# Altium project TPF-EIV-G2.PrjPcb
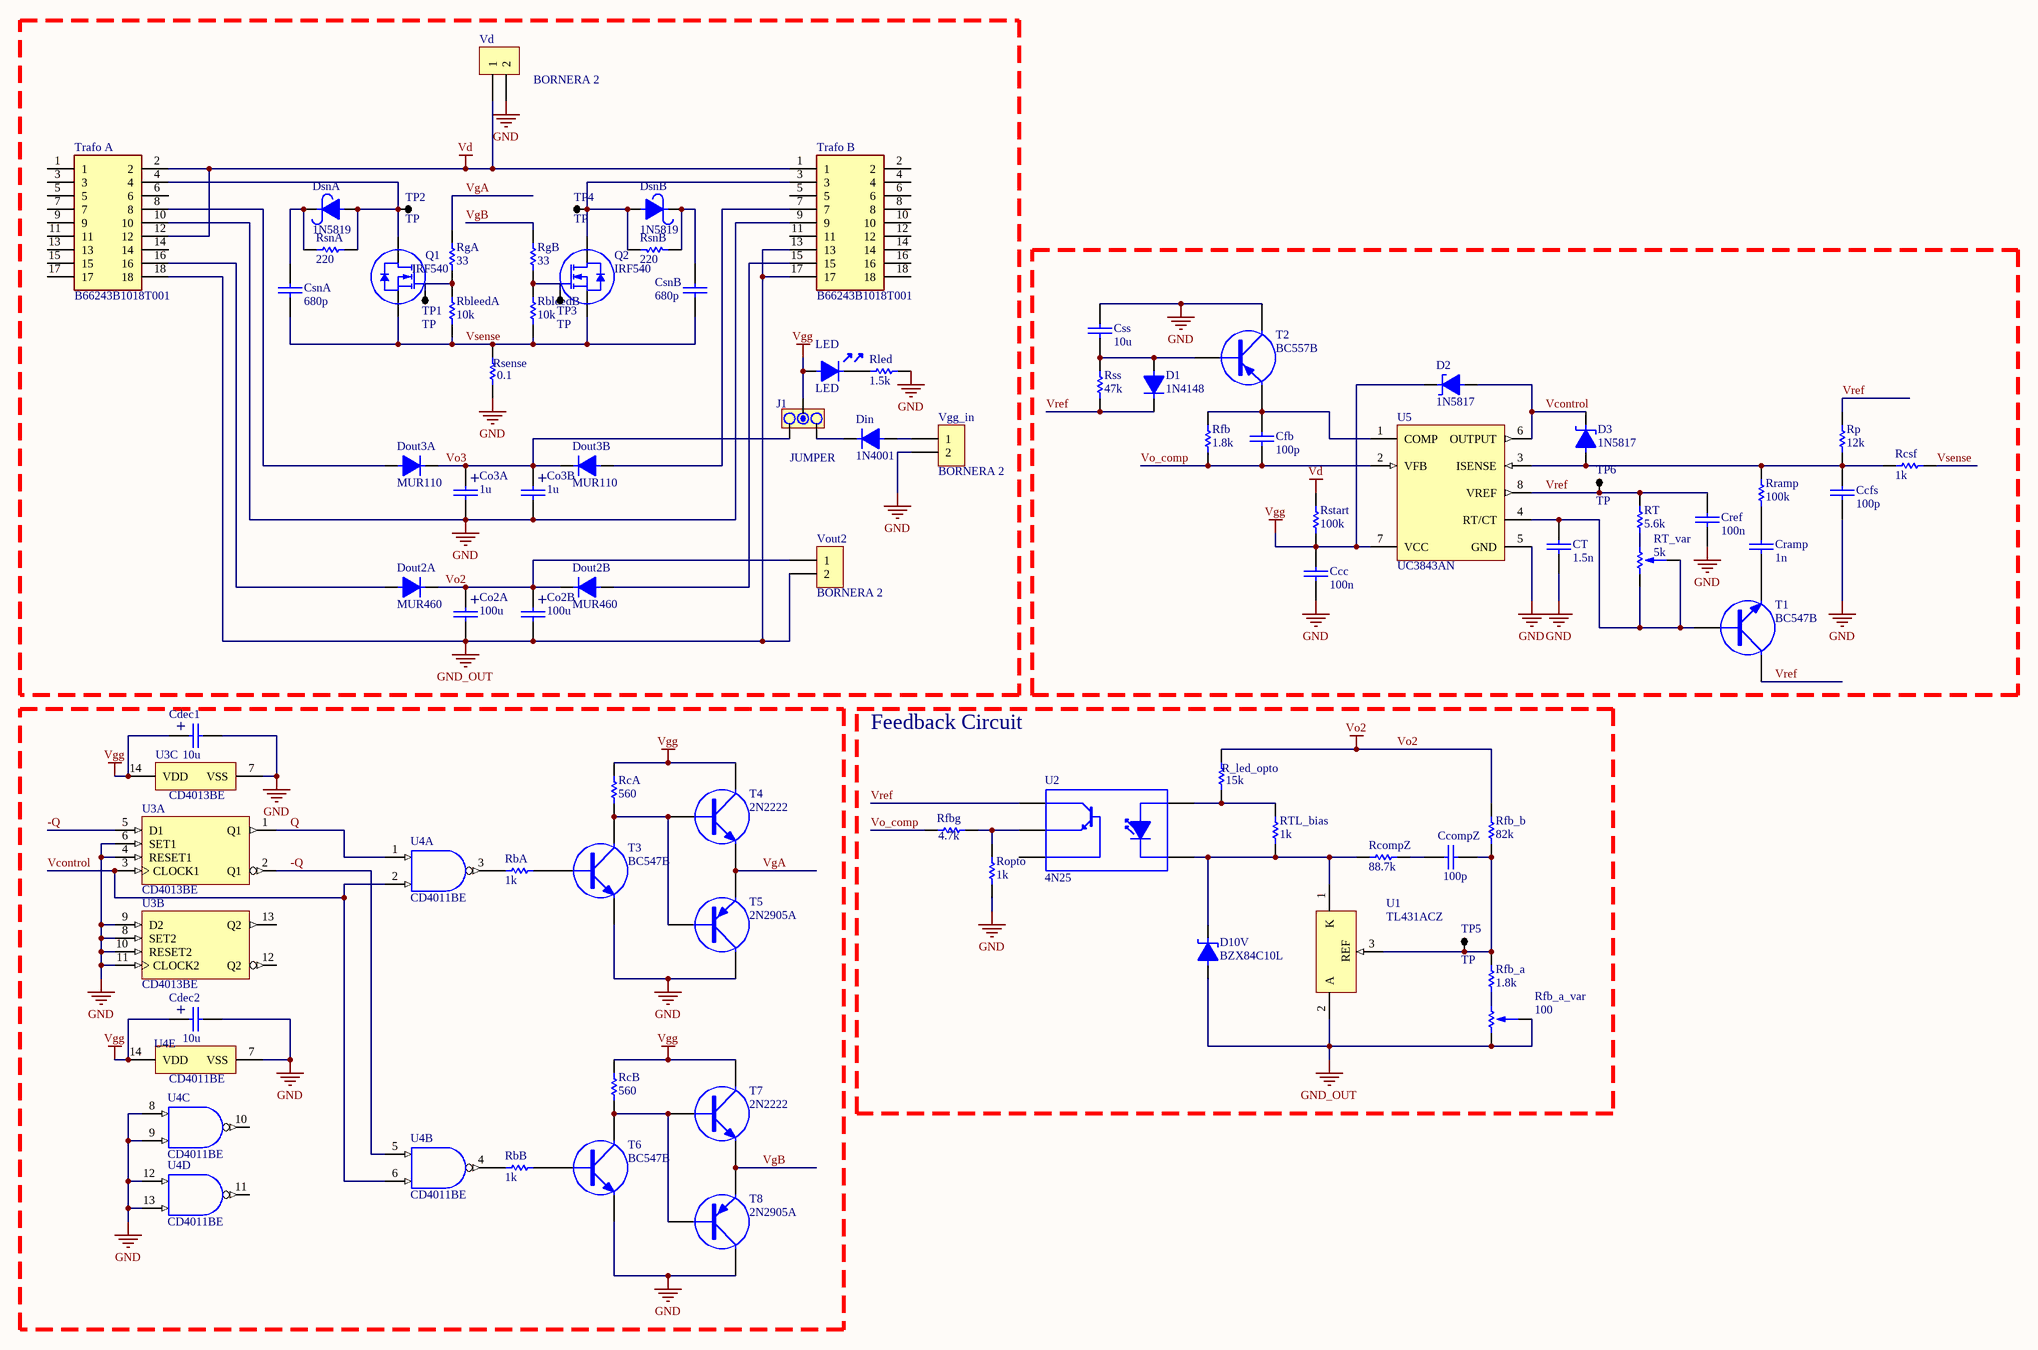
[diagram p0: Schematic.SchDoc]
1 sheet, 83 parts. Net scope: global (net labels, ports and power ports of the same name join across sheets).

## Sheet Schematic.SchDoc
size A0; SheetNumber: 1; SheetTotal: 1

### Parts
Ccc  100n  [CAP100]
Ccfs  100p  [CAP100]
CcompZ  100p  [CAP100]
Cdec1  10u  [CAP100RP2]
Cdec2  10u  [CAP100RP2]
Cfb  100p  [CAP100]
Co2A  100u  [CAP300RP]
Co2B  100u  [CAP300RP]
Co3A  1u  [CAP100RP]
Co3B  1u  [CAP100RP]
Cramp  1n  [CAP100]
Cref  100n  [CAP100]
CsnA  680p  [CAP200]
CsnB  680p  [CAP200]
Css  10u  [CAP100]
CT  1.5n  [CAP100]
D1  1N4148  [DO41]
D2  1N5817  [DO41]
D3  1N5817  [DO41]
D10V  BZX84C10L  [DO41]
Din  1N4001  [DO41]
Dout2A  MUR460  [DO41]
Dout2B  MUR460  [DO41]
Dout3A  MUR110  [DO41]
Dout3B  MUR110  [DO41]
DsnA  1N5819  [DO41]
DsnB  1N5819  [DO41]
J1  JUMPER  [JUMPER3]
LED  LED  [LED3]
Q1  IRF540  [TO-220 V]
Q2  IRF540  [TO-220 V]
R_led_opto  15k  [RES400]
RbA  1k  [RES400]
RbB  1k  [RES400]
RbleedA  10k  [RES400]
RbleedB  10k  [RES400]
RcA  560  [RES400]
RcB  560  [RES400]
RcompZ  88.7k  [RES400]
Rcsf  1k  [RES400]
Rfb  1.8k  [RES400]
Rfb_a  1.8k  [RES400]
Rfb_a_var  100  [PRESET V]
Rfb_b  82k  [RES400]
Rfbg  4.7k  [RES400]
RgA  33  [RES400]
RgB  33  [RES400]
Rled  1.5k  [RES400]
Ropto  1k  [RES400]
Rp  12k  [RES400]
Rramp  100k  [RES400]
Rsense  0.1  [RES400]
RsnA  220  [RES600]
RsnB  220  [RES600]
Rss  47k  [RES400]
Rstart  100k  [RES400]
RT  5.6k  [RES400]
RT_var  5k  [PRESET V]
RTL_bias  1k  [RES400]
T1  BC547B  [TO92]
T2  BC557B  [TO92]
T3  BC547B  [TO92]
T4  2N2222  [TO92]
T5  2N2905A  [TO92]
T6  BC547B  [TO92]
T7  2N2222  [TO92]
T8  2N2905A  [TO92]
TP1  TP  [TPTH]
TP2  TP  [TPTH]
TP3  TP  [TPTH]
TP4  TP  [TPTH]
TP5  TP  [TPTH]
TP6  TP  [TPTH]
Trafo_A  B66243B1018T001  [B66243B1018T001]
Trafo_B  B66243B1018T001  [B66243B1018T001]
U1  TL431ACZ  [TO-92]
U2  4N25  [DIP6]
U3  CD4013BE  [N0014A]  (parts A,B,C of 3)
U4  CD4011BE  [N0014A]  (parts A,B,C,D,E of 5)
U5  UC3843AN  [P0008A]
Vd  BORNERA 2  [BORNERA2]
Vgg_in  BORNERA 2  [BORNERA2]
Vout2  BORNERA 2  [BORNERA2]

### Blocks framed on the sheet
Feedback Circuit: CcompZ D10V R_led_opto RcompZ Rfb_a Rfb_a_var Rfb_b Rfbg Ropto RTL_bias TP5 U1 U2

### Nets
GND: Ccc.1 Ccfs.1 Cdec1.2 Cdec2.2 Co3A.2 Co3B.2 Cref.1 Css.1 CT.1 Rled.1 Ropto.1 Rsense.2 T2.2(C) T3.3(E) T5.2(C) T6.3(E) T8.2(C) Trafo_A.10 Trafo_B.9 U3.4(RESET1) U3.6(SET1) U3.7(VSS) U3.8(SET2) U3.9(D2) U3.10(RESET2) U3.11(CLOCK2) U4.7(VSS) U4.8(E) U4.9(F) U4.12(G) U4.13(H) U5.5(GND) Vd.2 Vgg_in.2
GND_OUT: Co2A.2 Co2B.2 D10V.1 Rfb_a_var.2 Rfb_a_var.3 Trafo_A.18 Trafo_B.13 Trafo_B.17 U1.2(A) Vout2.2
Vd: Rstart.2 Trafo_A.2 Trafo_A.12 Trafo_B.1 Vd.1
Vgg: Ccc.2 Cdec1.1 Cdec2.1 D2.2 J1.2 LED.1 RcA.1 RcB.1 Rstart.1 T4.2(C) T7.2(C) U3.14(VDD) U4.14(VDD) U5.7(VCC)
Vo2: Co2A.1 Co2B.1 Dout2A.2 Dout2B.2 R_led_opto.2 Rfb_b.2 Vout2.1
-Q: U3.2(Q1) U3.5(D1) U4.5(C)
Q: U3.1(Q1) U4.1(A)
Vcontrol: D2.1 D3.2 U3.3(CLOCK1) U4.2(B) U4.6(D) U5.6(OUTPUT)
VgA: RgA.1 T4.3(E) T5.3(E)
VgB: RgB.1 T7.3(E) T8.3(E)
Vo3: Co3A.1 Co3B.1 Dout3A.2 Dout3B.2 J1.1
Vo_comp: Cfb.1 Rfb.1 Rfbg.1 U5.2(VFB)
Vref: Cref.2 D1.2 Rp.2 Rss.2 RT.2 T1.2(C) TP6.1 U2.5(C) U5.8(VREF)
Vsense: CsnA.1 CsnB.1 Q1.3(S) Q2.3(S) RbleedA.2 RbleedB.2 Rcsf.1 Rsense.1
NetCcfs_2: Ccfs.2 D3.1 Rcsf.2 Rp.1 Rramp.2 U5.3(ISENSE)
NetCcompZ_1: CcompZ.1 RcompZ.2
NetCcompZ_2: CcompZ.2 Rfb_a.2 Rfb_b.1 TP5.1 U1.3(REF)
NetCfb_2: Cfb.2 Rfb.2 T2.3(E) U5.1(COMP)
NetCramp_1: Cramp.1 T1.3(E)
NetCramp_2: Cramp.2 Rramp.1
NetCsnA_2: CsnA.2 DsnA.2 RsnA.1
NetCsnB_2: CsnB.2 DsnB.2 RsnB.1
NetCss_2: Css.2 D1.1 Rss.1 T2.1(B)
NetCT_2: CT.2 RT_var.2 RT_var.3 T1.1(B) U5.4(RT/CT)
NetD10V_2: D10V.2 RcompZ.1 RTL_bias.1 U1.1(K) U2.2(K)
NetDin_1: Din.1 Vgg_in.1
NetDin_2: Din.2 J1.3
NetDout2A_1: Dout2A.1 Trafo_A.16
NetDout2B_1: Dout2B.1 Trafo_B.15
NetDout3A_1: Dout3A.1 Trafo_A.8
NetDout3B_1: Dout3B.1 Trafo_B.7
NetDsnA_1: DsnA.1 Q1.2(D) RsnA.2 TP2.1 Trafo_A.4
NetDsnB_1: DsnB.1 Q2.2(D) RsnB.2 TP4.1 Trafo_B.3
NetLED_2: LED.2 Rled.2
NetQ1_1: Q1.1(G) RbleedA.1 RgA.2 TP1.1
NetQ2_1: Q2.1(G) RbleedB.1 RgB.2 TP3.1
NetR_led_opto_1: R_led_opto.1 RTL_bias.2 U2.1(A)
NetRbA_1: RbA.1 T3.1(B)
NetRbA_2: RbA.2 U4.3(J)
NetRbB_1: RbB.1 T6.1(B)
NetRbB_2: RbB.2 U4.4(K)
NetRcA_2: RcA.2 T3.2(C) T4.1(B) T5.1(B)
NetRcB_2: RcB.2 T6.2(C) T7.1(B) T8.1(B)
NetRfb_a_1: Rfb_a.1 Rfb_a_var.1
NetRfbg_2: Rfbg.2 Ropto.2 U2.4(E)
NetRT_1: RT.1 RT_var.1

Not connected (* = marked no-connect by the designer): Trafo_A 1 3 5 6 7 9 11 13 14 15 17; Trafo_B 2 4 5 6 8 10 11 12 14 16 18; U2 6(B); U3 12(Q2) 13(Q2); U4 10(L) 11(M)

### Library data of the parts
Ccc Ccfs CcompZ Cfb Cramp Cref CsnA CsnB Css CT = CAP
Cdec1 Cdec2 Co2A Co2B Co3A Co3B = CAPPOL
D1 Din Dout2A Dout2B Dout3A Dout3B = DIODO
D2 D3 D10V = DIODO ZENER
DsnA DsnB = DIODO SCHOTTKY
J1 = JUMPER3
Q1 Q2 = MOSFET N
R_led_opto RbA RbB RbleedA RbleedB RcA RcB RcompZ Rcsf Rfb Rfb_a Rfb_b Rfbg RgA RgB Rled Ropto Rp Rramp Rsense RsnA RsnB Rss Rstart RT RTL_bias = RES
Rfb_a_var RT_var = PRESET
T1 T3 T4 T6 T7 = TRANSISTOR NPN
T2 T5 T8 = TRANSISTOR PNP
Trafo_A Trafo_B = B66243B1018T001: Inductor; Manufacturer_Name: TDK
U1 = CMP-0242-00006-1: Programmable Voltage Reference, 2.5 to 36V, 3-Pin TO-92
U3 = CMP-1619-00744-2: CMOS Dual D-Type Flip Flop, N0014A, TUBE; Manufacturer: Texas Instruments; Schmitt Trigger: No; F @ Nom Voltage(Max)(Mhz): 8; tpd @ Nom Voltage(Max)(ns): 130; Output Logic: Inverted,Non-inverted; Rating: Military; Technology Family: CD4000; Voltage(Nom)(V): 10; Bits(#): 2; Output Drive (IOL/IOH)(Max)(mA): 1.5/-1.5; VCC(Min)(V): 3; VCC(Max)(V): 18; ICC @ Nom Voltage(Max)(mA): 0.06
U4 = CMP-1627-00488-2: CMOS Quad 2-Input NAND Gate, N0014A, TUBE; Manufacturer: Texas Instruments; Schmitt Trigger: No; Bits(#): 4; Voltage(Nom)(V): 10; Output Drive (IOL/IOH)(Max)(mA): 1.5/-1.5; ICC @ Nom Voltage(Max)(mA): 0.015; Technology Family: CD4000; VCC(Max)(V): 18; Rating: Military; VCC(Min)(V): 3; F @ Nom Voltage(Max)(Mhz): 8
U5 = CMP-0319-00327-2: PWM Controller with Current Control, 100 % Duty Cycle, 0 to +70 degC, 8-pin PDIP (P), Green (RoHS & no Sb/Br); Manufacturer: Texas Instruments; Duty Cycle(Max)(%): 100; Regulated Outputs(#): 1; Rating: Catalog; Topology: Boost, Buck, Flyback, Forward; Frequency(Max)(kHz): 450; UVLO Thresholds On/Off(V): 8.4/7.6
